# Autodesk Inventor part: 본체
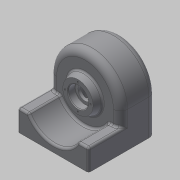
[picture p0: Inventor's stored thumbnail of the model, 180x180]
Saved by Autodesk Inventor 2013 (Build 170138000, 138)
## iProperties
Created: 2015-02
Part Number: 본체
Material: 일반
Document SubType Name: Modeling
Designer: Administrator
Density: 1 g/cm^3
Author: Administrator
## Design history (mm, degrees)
sketch "스케치1"
  geometry: L1 (-50, -50)-(50, -50); L2 (50, -50)-(50, 50); L3 (50, 50)-(-50, 50); L4 (-50, 50)-(-50, -50); L5 (-50, -50)-(50, 50); L6 (50, -50)-(-50, 50); 1 further point
  constraints: 12 end point, 2 midpoint, 2 parallel, 1 horizontal, 1 perpendicular
  dimensions: "d0" = 100 distance of L3.end L2.end; "d1" = 100 distance of L2.end L1.end
extrude "돌출1" new body sketch "스케치1" distance "d2" = 50; taper "d3" = 0 deg
fillet "모깎기1" dims "d4" = 50
feature "쉘1" dims "d5" = 4
sketch "스케치2"
  geometry: C1 r 25 at (0, 0); A1 r 50 centre (0, 0) between (50, 0) and (-50, 0) reference
  constraints: 1 centre point, 1 coincident
  dimensions: "d6" = 50 diameter of C1
extrude "돌출2" join sketch "스케치2" distance "d7" = 10; taper "d8" = -20 deg
hole "구멍1" diameter "d11" = 20; stored, may be unused: countersink angle "d15" = 90 deg, drill point angle "d17" = 0 deg; dims "d9" = 10, "d10" = 10, "d12" = 6, "d13" = 28, "d14" = 10, "d16" = 4
sketch "스케치3"
  geometry: C1 r 20 at (0, 0); A1 r 50 centre (0, 0) between (50, 0) and (-50, 0) reference
  constraints: 1 centre point, 1 coincident
  dimensions: "d18" = 40 diameter of C1
extrude "돌출3" join sketch "스케치3" distance "d19" = 9; taper "d20" = 0 deg
hole "구멍2" diameter "d23" = 20; stored, may be unused: countersink angle "d27" = 90 deg, drill point angle "d29" = 0 deg; dims "d21" = 10, "d22" = 10, "d24" = 6, "d25" = 28, "d26" = 8, "d28" = 2
sketch "스케치4"
  geometry: L1 (-50, 0)-(-50, -50) reference; L2 (-50, -50)-(50, -50) reference; L3 (50, -50)-(50, 0) reference; L4 (-50, -50)-(50, -50); L5 (50, -20)-(34.641, -20); L6 (-50, -50)-(-50, -20); L7 (-50, -20)-(-34.641, -20); L8 (50, -50)-(50, -20); A1 r 50 centre (0, 0) between (50, 0) and (-50, 0) reference; A2 r 40 centre (0, 0) between (-34.641, -20) and (34.641, -20)
  constraints: 10 end point, 3 collinear, 2 point on circle, 2 point on line, 1 centre point, 1 coincident, 1 parallel, 1 perpendicular
  dimensions: "d30" = 40 radius of A2; "d31" = 30 distance between parallel lines of L2 L5
extrude "돌출4" join sketch "스케치4" distance "d32" = 45; taper "d33" = 0 deg
fillet "모깎기2" dims "d34" = 10, "d35" = 6
fillet "모깎기3" dims "d36" = 0.3, "d37" = 3
chamfer "모따기1" distance "d38" = 1; stored, may be unused: second distance "d39" = 2, angle "d40" = 45 deg
fillet "모깎기4" dims "d41" = 3
sketch "스케치5" dims "d42" = 36
  geometry: C1 r 15 at (0, 0) reference; 2 further points
  constraints: 2 vertical alignment, 1 coincident, 2 other
hole "구멍3" sketch "스케치5" at (0, 18) diameter "d43" = 2.459; stored, may be unused: countersink angle "d47" = 90 deg, drill point angle "d49" = 118 deg; dims "d44" = 6, "d45" = 4, "d46" = 2, "d48" = 9
sketch "스케치6"
  geometry: L1 (90, 10)-(90, 92) reference; L2 (-7, 95)-(87, 95) reference; 2 further points
  dimensions: "d53" = 9 distance from line of L2 point (81.75, 86); "d54" = 8.25 distance from line of L1 point (81.75, 86)
hole "구멍4" sketch "스케치6" at (81.75, 86) diameter "d55" = 5.134; stored, may be unused: countersink angle "d59" = 90 deg, drill point angle "d61" = 118 deg; dims "d56" = 10, "d57" = 4, "d58" = 2, "d60" = 13
node "솔리드1"
pattern_circular "원형 패턴1" dims angle "d51" = 360 deg
pattern_linear "직사각형 패턴1" dims "d64" = 33, "d67" = 83.5
